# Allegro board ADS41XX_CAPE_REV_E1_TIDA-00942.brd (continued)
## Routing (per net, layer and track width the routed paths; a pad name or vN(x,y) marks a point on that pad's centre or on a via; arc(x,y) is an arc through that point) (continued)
P4.7V: length 8
  TOP w0.305: 39.75,105.28 39.92,105.12 U7.1
  TOP w0.508: C78.1 v1(40.51,107.44) FB6.2 39.75,107.26 v1(39.75,106.05) 39.75,105.28 C79.1 R83.1
  vias: v1(38.48,108.84) v1(38.48,107.44) v1(38.73,106.05) v1(39.62,108.84) v1(40.26,105.41) v1(40.51,108.84) v1(40.51,106.55) v1(40.89,106.17) v1(41.53,108.84) v1(41.66,106.17)
VDD_5V: length 16.1
  PWR2 w0.559: J6.5 53.49,23.98 ; J6.5 53.49,25.55 ; J6.5 51.92,23.98 ; J6.5 51.92,25.55 ; JP4.1 44.64,34.35 ; JP4.1 42.99,32.7 ; JP4.1 43.81,34.67 43.69,34.8 ; JP4.1 43.81,32.89 43.43,32.51 ; JP4.1 44.64,32.7 ; JP4.1 42.99,34.35 ; 49.38,25.55 J6.6 ; J6.6 50.95,25.55 ; J6.6 49.38,23.98 ; J6.6 50.95,23.98
VIN-: length 5.3
  TOP w0.381: v1(25.78,92.2) 26.26,92.69 U6.2 26.26,95.99 R57.1
  BOTTOM w0.381: R16.1 v1(25.78,92.2)
AIN_P: length 3.2
  TOP w0.381: R9.2 24.99,95.94 C11.1 U6.3
AINP: length 13
  TOP w0.381: C62.1 R56.2 ; R56.2 R10.1 ; R56.2 JP5.1 J1.1
AVP: length 4.6
  TOP w0.381: R9.1 D1.3 R10.2
B+: length 1.2
  TOP w0.279: U5.10 24.89,72.49 R1.1
B-: length 1.2
  TOP w0.279: R3.1 25.39,72.46 U5.11
BBB-CLKOUT: length 51.8
  TOP w0.178: v1(42.8,48.51) 46.62,48.51 46.71,48.6 49.19,48.6 J6.24 50.16,50.16 ; RN2.16 v1(11.51,40.59)
  BOTTOM w0.178: v1(42.8,48.51) 39.37,45.09 31.88,45.09 31,44.21 31,40.65 29.84,39.5 27.81,39.5 25.91,37.59 13.08,37.59 11.51,39.17 v1(11.51,40.59)
BBB-D0: length 27.5
  TOP w0.178: 4.45,75.56 8.76,75.56 10.79,73.53 10.79,57.15 12.98,54.97 RN1.9
BBB-D1: length 30.1
  TOP w0.178: RN1.10 12.29,53.34 10.03,55.6 10.03,72.39 8.26,74.17 3.3,74.17 1.91,75.56
BBB-D2: length 26.1
  TOP w0.178: 4.45,73.03 7.37,73.03 9.4,70.99 9.4,55.42 12.29,52.53 RN1.11
BBB-D3: length 28.6
  TOP w0.178: 1.91,73.03 3.17,71.75 7.11,71.75 8.89,69.98 8.89,55.12 12.29,51.71 RN1.12
BBB-D4: length 25
  TOP w0.178: 4.45,70.48 6.99,70.48 8.26,69.22 8.26,54.94 12.29,50.9 RN1.13
BBB-D5: length 27.8
  TOP w0.178: RN1.14 12.29,50.09 7.75,54.64 7.75,68.71 7.37,69.09 3.3,69.09 1.91,70.48
BBB-D6: length 23
  TOP w0.178: RN1.15 12.29,49.28 7.11,54.46 7.11,65.91 5.08,67.94 4.45,67.94
BBB-D7: length 25.8
  TOP w0.178: RN1.16 12.29,48.46 6.6,54.15 6.6,65.53 5.46,66.67 3.17,66.67 1.91,67.94
BBB-D8: length 11.2
  TOP w0.178: RN2.9 10.87,46.28 4.45,52.7
BBB-D9: length 15.1
  TOP w0.178: RN2.10 13.67,45.47 13.84,45.64 13.84,47.07 13.67,47.24 12.45,47.24 4.45,55.24
BBB-D10: length 17.2
  TOP w0.178: RN2.11 7.67,44.65 6.1,46.23 3.68,46.23 2.92,46.99 2.92,51.31 1.91,52.32 1.91,52.7
BBB-D11: length 23.8
  TOP w0.178: 1.91,55.24 0.89,54.23 0.89,44.07 1.12,43.84 RN2.12
BBB-SCLK: length 70.9
  TOP w0.178: U11.6 15.99,88 16.76,88.77 v1(17.65,89.53)
  BOTTOM w0.178: v1(17.65,89.53) 17.87,89.75 18.12,89.75 19.16,90.79 24.09,90.79 24.65,91.35 25.34,91.35 25.57,91.12 25.89,91.12 26.01,91 26.38,91 26.58,90.79 46.33,90.79 48.59,88.53 48.59,86.92 49.14,86.37 49.14,83.36 48.01,82.23 48.01,78.36 49.02,77.34 49.02,59.56 49.53,59.05 51.44,59.05 52.7,57.78
BBB-SDATA: length 81.5
  TOP w0.178: U11.10 11.46,89 v1(11.43,91.44)
  BOTTOM w0.178: v1(11.43,91.44) 11.44,91.45 17.39,91.45 17.65,91.19 24.02,91.19 24.52,91.68 25.47,91.68 25.7,91.45 26.02,91.45 26.15,91.33 26.51,91.33 26.65,91.19 48.13,91.19 48.64,90.68 48.64,88.95 48.92,88.67 48.92,87.73 49.53,87.12 49.53,84.23 49.47,84.16 49.47,83.48 49.53,83.41 49.53,80.92 49.47,80.86 49.47,80.18 49.53,80.11 49.53,78.23 51.44,76.33 51.44,60.07 52.58,58.93 53.21,58.93 53.59,58.55 53.59,58.28 53.68,58.19 53.68,57.38 53.59,57.29 53.59,56.64 53.34,56.39 51.31,56.39 50.16,55.24
BBB-SDOUT: length 94.6
  TOP w0.178: U11.13 v1(10.29,87)
  BOTTOM w0.178: v1(10.29,87) 7.37,87 6.6,87.76 6.6,91.31 7.75,92.46 10.16,92.46 10.92,91.69 10.92,91.19 11.3,90.81 11.56,90.81 11.87,91.12 15.18,91.12 17.26,89.04 18.94,89.04 19.32,89.42 21.22,89.42 21.84,90.04 23.81,90.04 24.79,91.02 25.2,91.02 25.43,90.79 25.75,90.79 25.99,90.55 26.35,90.55 26.86,90.04 30.86,90.04 30.99,89.92 33.59,89.92 33.7,89.8 34.43,89.8 35.05,90.42 45.72,90.42 48.26,87.88 48.26,84.84 48.25,84.82 48.25,84.44 47.24,83.44 47.24,77.09 48.59,75.74 48.59,61.33 48.39,61.13 48.39,57.4 49.02,56.77 49.02,54.48 49.53,53.98 51.44,53.98 52.7,55.24
BBB-SEN: length 65.9
  TOP w0.178: v1(42.42,83.82) 36.58,83.82 36.45,83.69 35.75,83.69 35.38,83.32 31.99,83.32 v1(31.62,83.69) ; U11.3 v1(15.23,86.5)
  BOTTOM w0.178: v1(31.62,83.69) 31.37,83.95 26.42,83.95 23.11,87.25 15.98,87.25 v1(15.23,86.5) ; v1(42.42,83.82) 44.2,82.04 44.2,77.6 44.96,76.83 45.97,76.83 47.37,75.44 47.5,75.44 48.26,74.68 48.26,61.47 47.37,60.58 47.37,57.53 48.39,56.52 48.39,53.98 49.66,52.7 50.16,52.7
CLK: length 1.4
  TOP w0.381: R25.1 U14.4
CLK+: length 10.7
  TOP w0.178: JP9.1 32.26,62.36
  TOP w0.279: 28.83,60.17 U1.10
  TOP w0.381: 28.83,60.17 30.86,60.17 arc(31.94,60.62) 32.38,61.69 JP9.1 32.38,64.01 33.53,65.15 C8.2
CLK-: length 2.2
  TOP w0.279: C10.1 28.7,60.96 28.41,60.67 U1.11
CLK_P: length 2.5
  TOP w0.381: U14.2 Y1.3
CLKOUT: length 17.9
  BOTTOM w0.178: R27.1 29.58,56.25 29.58,53.61 30.67,52.51 30.67,42.86 29.59,41.78 27.16,41.78 U3.23
CLOCK: length 3.9
  TOP w0.381: Y1.1 R24.2 39.88,57.15 JP7.1
CLOCKIN: length 11.7
  TOP w0.381: R18.1 44.07,78.81 arc(45.05,81.19) 47.42,82.17 J3.1
CN: length 15.7
  TOP w0.381: R18.2 44.07,73.51 arc(44,73.18) 43.81,72.9 arc(43.11,72.43) 42.28,72.26 37.34,72.26 arc(35.81,71.63) 35.18,70.1 JP8.3
CP: length 6.4
  TOP w0.381: R25.2 41.66,69.85 arc(40.67,69.44) 40.26,68.45 JP8.1
D0: length 8.2
  TOP w0.178: U1.37 20.87,53.51 v1(20.83,53.47)
  BOTTOM w0.178: U3.2 24.72,52.24 23.5,53.47 v1(20.83,53.47)
D1: length 8.3
  TOP w0.178: U1.38 21.34,54.86 v1(21.34,52.83)
  BOTTOM w0.178: U3.3 22.43,51.74 v1(21.34,52.83)
D2: length 9.5
  TOP w0.178: v1(21.78,50.74) 21.78,52.57 21.83,52.63 21.83,54.85 U1.39
  BOTTOM w0.178: U3.5 v1(21.78,50.74)
D3: length 9.4
  TOP w0.178: U1.40 22.4,54.86 v1(22.4,50.24)
  BOTTOM w0.178: U3.6 v1(22.4,50.24)
D4: length 10.6
  TOP w0.178: v1(22.61,49.02) 22.61,49.66 22.87,49.92 22.87,50.01 22.9,50.03 22.9,50.45 22.87,50.47 U1.41
  BOTTOM w0.178: v1(22.61,49.02) 22.99,49.02 23.11,49.15 27.03,49.15 U3.8
D5: length 11.7
  TOP w0.178: U1.42 23.37,54.89 23.37,51.18 23.24,51.05 23.24,48.77 22.73,48.26 v1(22.73,48.13)
  BOTTOM w0.178: U3.9 23.34,48.74 v1(22.73,48.13)
D6: length 10.7
  TOP w0.178: U1.43 23.87,50.92 23.62,50.67 v1(23.62,47.88)
  BOTTOM w0.178: v1(23.62,47.88) 25.4,47.88 25.53,47.75 27.11,47.75 U3.11
D7: length 12.6
  TOP w0.178: v1(23.12,47.24) 23.74,47.24 24.13,47.62 24.13,50.67 24.38,50.93 24.38,54.88 U1.44
  BOTTOM w0.178: U3.12 v1(23.12,47.24)
D8: length 12
  TOP w0.178: v1(23.75,46.74) 24.46,47.45 24.46,50.37 24.87,50.78 U1.45
  BOTTOM w0.178: U3.13 27.11,46.74 v1(23.75,46.74)
D9: length 11.6
  TOP w0.178: v1(24.52,46.24) 24.52,47.04 24.79,47.31 24.79,50.19 25.4,50.8 25.4,54.87 U1.46
  BOTTOM w0.178: U3.14 v1(24.52,46.24)
D10: length 12.1
  TOP w0.178: v1(25.02,45.21) 25.02,47.07 25.12,47.17 25.12,50.05 25.87,50.81 U1.47
  BOTTOM w0.178: U3.16 27.09,45.21 v1(25.02,45.21)
D11: length 14.8
  TOP w0.178: U1.48 26.37,54.15 v1(26.8,53.72)
  BOTTOM w0.178: U3.17 28.87,44.74 29.75,45.62 29.75,52.67 28.7,53.72 v1(26.8,53.72)
DATA_OE: length 49.7
  TOP w0.178: v1(20.92,41.24) 21.63,41.24 22.86,40.01 43.31,40.01 50.16,33.15 J6.12
  TOP w0.33: v1(20.92,41.24) R41.2
  BOTTOM w0.178: U3.48 20.62,52.74 21.08,52.28 21.08,50.29 21.46,49.91 21.46,41.78 v1(20.92,41.24)
  BOTTOM w0.33: U3.25 v1(20.92,41.24)
DBIN+: length 1
  TOP w0.381: L2.1 R1.2
DBIN-: length 1
  TOP w0.381: L3.1 R3.2
DBIN_N: length 3.6
  TOP w0.381: L3.2 25.63,68.4 R14.1 C56.2 25.63,65.35 R54.1
DBIN_P: length 3.6
  TOP w0.381: R53.1 24.61,65.35 C56.1 R14.2 24.61,68.4 L2.2
DFS: length 7.1
  TOP w0.178: JP6.2 32.77,58.29 31.68,58.29 31.67,58.31 30.82,58.31 30.8,58.29 29.59,58.29 29.47,58.17 U1.6
I2C2_SCL: length 50.5
  TOP w0.178: R20.2 v1(45.09,86.23) U15.6
  PWR1 w0.178: v1(45.09,86.23) 45.09,86.11 49.01,82.18 49.01,80.57 48.9,80.45 48.9,44.5 49.58,43.81 51.44,43.81 J6.19
I2C2_SDA: length 47.2
  TOP w0.178: R15.2 45.85,84.96 v1(45.09,84.96) U15.5
  PWR1 w0.178: J6.20 50.04,42.55 48.41,44.17 48.41,79.73 45.09,83.06 v1(45.09,84.96)
IN+: length 9.4
  TOP w0.279: C3.2 25.39,76.84 U5.2
  TOP w0.381: C3.2 25.64,79.11 v1(26.04,79.5) ; R6.2 C2.1 29.13,79.58 v1(29.21,79.5)
  BOTTOM w0.381: v1(26.04,79.5) v1(29.21,79.5)
IN-: length 5.1
  TOP w0.279: U5.3 24.89,76.84 C3.1
  TOP w0.381: C99.1 R5.2 23.3,78.61 24.26,78.61 24.63,78.24 C3.1
IN_M: length 2.5
  TOP w0.178: U1.16 24.87,62.63 24.97,62.73 24.97,63.73 R53.2
IN_P: length 2.5
  TOP w0.178: R54.2 25.27,63.73 25.27,62.73 25.37,62.63 U1.15
INM: length 3.6
  TOP w0.381: R7.1 27.15,79.71 R6.1 C1.2 R11.1
INP: length 6.9
  TOP w0.381: R8.2 24.99,80.85 C1.1 R17.1 23.25,80.82 R5.1
N4.7V:
  vias: v1(4.57,99.31) v1(5.71,99.31) v1(6.6,99.57) v1(6.99,100.71) v1(6.99,98.81) v1(7.11,100.08) v1(7.11,97.92) v1(7.24,99.44) v1(7.62,98.68) v1(7.75,99.95) v1(7.87,100.71)
OUT+: length 7.4
  TOP w0.381: v1(24.99,90.53) U6.6 24.99,86.79 R8.1
  BOTTOM w0.381: v1(24.99,90.53) 25.99,89.53 26.67,89.53 R16.2
OVR/SDOUT: length 45.7
  TOP w0.178: TP3.1 33.02,51.56 30.86,53.72 30.86,55.37 29.56,56.67 v1(28.57,56.67) U1.3 ; U10.11 12.23,73.49 13.84,71.88 13.84,69.34 v1(14.1,69.09)
  BOTTOM w0.178: v1(14.1,69.09) 21.84,69.09 22.35,68.58 28.96,68.58 29.59,67.94 29.59,65.66 29.34,65.41 29.34,58.67 28.45,57.78 28.45,56.8 v1(28.57,56.67)
RESET: length 39.2
  TOP w0.178: U1.30 v1(14.47,58.67) ; v1(2.79,84.2) 5.07,84.2 U13.4
  BOTTOM w0.178: v1(2.79,84.2) R88.2 2.79,77.39 2.97,77.22 4.45,77.22 10.73,70.93 10.73,63.18 14.47,59.44 v1(14.47,58.67)
SCLK: length 23.6
  TOP w0.178: U10.13 13.46,77.11 v1(13.46,75.31) ; v1(16.51,59.17) U1.29
  BOTTOM w0.178: v1(13.46,75.31) 13.08,74.93 13.08,65.79 TP16.1 16.51,61.34 v1(16.51,59.17)
SDATA: length 34.7
  TOP w0.178: U1.28 17.04,59.67 15.49,61.21 15.49,63.25 17.53,65.28 TP17.1 14.73,68.2 14.73,72.39 12.88,74.24 U10.12 12.88,78.81 11.94,79.76 5.97,79.76 JP1.2
SEN: length 24.4
  TOP w0.178: U1.27 17.81,60.17 17.02,60.96 17.02,62.36 17.91,63.25 19.56,63.25 20.07,63.75 20.07,67.94 TP15.1 16.71,71.12 14.18,73.65 U10.14
SPARE1: length 7.8
  TOP w0.178: 1.91,34.92 3.17,33.66 6.74,33.66 7.38,33.02 PP5.1
SPARE2: length 7.8
  TOP w0.178: PP4.1 7.38,38.1 6.74,38.73 3.17,38.73 1.91,37.47
SPI-ACT: length 16.1
  TOP w0.178: 9.4,84.84 9.4,86.23 8.81,86.82 U13.1 ; U10.9 v1(9.56,77.19) ; 9.4,82.3 9.4,81.41 v1(9.56,81.25) 7.4,81.25 JP3.1
  TOP w0.254: 9.4,84.84 9.4,83.95 R86.2 9.4,82.93 9.4,82.3
  BOTTOM w0.178: v1(9.56,77.19) v1(9.56,81.25)
SW1_A0: length 7.2
  TOP w0.178: SW1.4 37.59,91.19 38.58,90.2 U15.1 36.2,88.77 R26.2
SW1_A1: length 13.1
  TOP w0.178: R23.2 36.2,87.5 U15.2 40.13,87.5 40.64,88.01 40.64,92.46 38.86,94.23 SW1.3
SW1_A2: length 2.5
  TOP w0.178: U15.3 R22.2
SYS_5V: length 27.7
  TOP w0.559: 37.91,34.35 JP4.3 ; JP4.3 37.91,32.7 ; JP4.3 38.73,34.92 ; JP4.3 38.73,32.51 38.61,32.38 ; J6.7 53.49,26.52 ; J6.7 51.92,28.09 ; J6.7 53.49,28.09 ; J6.7 51.92,26.52 ; 49.38,28.09 J6.8 ; J6.8 50.95,28.09 ; J6.8 50.95,26.52 ; J6.8 49.38,26.52
  TOP w1.524: J6.8 J6.7
  PWR2 w0.559: J6.7 53.49,28.09 ; J6.7 51.92,26.52 ; J6.7 51.92,28.09 ; 37.91,32.7 JP4.3 ; JP4.3 39.56,34.35 ; JP4.3 37.91,34.35 ; J6.8 50.95,28.09 ; J6.8 50.95,26.52 ; J6.8 49.38,26.52 ; J6.8 49.38,28.09
USB-SCLK: length 94.6
  TOP w0.178: U11.5 16.25,87.5 16.45,87.69 18.99,87.69 v1(19.18,87.88) ; U2.5 v1(43.28,23.22)
  BOTTOM w0.178: v1(43.28,23.22) 43.28,25.49 46.3,28.51 46.3,35.25 44.58,36.96 44.58,49.4 44.96,49.78 44.96,68.71 44.45,69.22 35.97,69.22 34.92,70.26 34.92,80.9 32.38,83.44 32.38,84.2 31.5,85.09 28.57,85.09 28.31,85.36 28.24,85.36 27.95,85.65 27.95,85.71 26.4,87.26 24.12,87.26 23.5,87.88 v1(19.18,87.88)
USB-SDATA: length 102.2
  TOP w0.178: U11.11 10.81,88 v1(10.79,88.01) ; U2.3 v1(44.58,23.24)
  BOTTOM w0.178: v1(10.79,88.01) 10.92,88.14 10.92,89.53 11.53,90.14 11.83,90.14 12.15,90.46 14.69,90.46 16.78,88.38 23.51,88.38 24.26,87.63 27.87,87.63 28.24,87.26 29.45,87.26 30.1,86.61 31.75,86.61 32.26,86.11 32.26,84.84 32.77,84.33 32.77,83.82 36.42,80.17 36.42,73.49 37.34,72.57 37.34,70.1 37.85,69.6 44.7,69.6 45.37,68.93 45.37,38.01 47.6,35.78 47.6,27.97 44.58,24.96 v1(44.58,23.24)
USB-SDOUT: length 111.7
  TOP w0.178: U2.1 v1(45.88,23.08) ; U11.14 v1(10.93,86.5)
  BOTTOM w0.178: v1(10.93,86.5) 10.93,87.11 10.03,88.01 7.37,88.01 7.11,88.27 7.11,91.06 7.87,91.82 10.16,91.82 10.59,91.39 10.59,91.05 11.17,90.47 11.69,90.47 12.01,90.79 15,90.79 17.08,88.71 23.81,88.71 24.38,88.14 27.66,88.14 27.8,88.28 29.22,88.28 29.35,88.4 31.1,88.4 32.64,86.87 32.64,85.22 37.23,80.63 37.23,79.61 41.91,74.93 43.94,74.93 44.7,74.17 44.7,73.15 46.1,71.75 46.1,59.36 45.93,59.19 45.93,58.78 46.1,58.61 46.1,39.12 48.9,36.32 48.9,27.43 45.88,24.42 v1(45.88,23.08)
USB-SEN: length 96.6
  TOP w0.178: U2.11 v1(39.38,23.23) ; U11.2 15.98,86 v1(16,85.98)
  BOTTOM w0.178: v1(16,85.98) 16.89,86.87 22.86,86.87 26.23,83.5 30.42,83.5 32.38,81.53 32.38,73.09 32.13,72.84 32.13,69.98 33.22,68.88 36.59,68.88 44.3,68.88 44.45,68.73 44.45,56.52 43.43,55.5 43.43,49.78 43.94,49.28 43.94,35.94 45.72,34.16 45.72,28.83 40.12,23.23 v1(39.38,23.23)
VCM: length 22.3
  TOP w0.178: U5.9 24.31,72.9 v1(23.24,72.9) ; v1(29.72,70.87) 29.72,66.29 27.94,64.52 27.94,64.14 26.8,62.99 v1(26.54,62.99) 26.37,62.82 U1.13
  TOP w0.381: U5.9 22.44,72.97 21.98,72.52
  BOTTOM w0.178: v1(26.54,62.99) 26.54,62.38 C21.1 ; v1(23.24,72.9) 24.26,71.88 28.32,71.88 29.34,70.87 v1(29.72,70.87)
N10245644: length 2.6
  TOP w0.178: v1(28.96,57.4) 28.69,57.67 U1.5
  BOTTOM w0.178: v1(28.96,57.4) 29.46,57.4 R27.2
N18756746: length 7.3
  TOP w0.254: U2.16 38.08,13.55 38.16,13.47 38.16,13.32 38.35,13.13 38.57,13.13 38.73,12.97 38.73,12.82 38.8,12.75 38.8,11.8 39.65,10.95 C26.1 39.65,10.27 39.71,10.21 J4.2
N18756762: length 11.3
  TOP w0.508: U2.20 40.68,13.04 40.89,12.83 43.69,12.83 FB1.2 46.25,11.3 46.27,11.32 C25.1 47.93,11.2 C24.1
N18756792: length 13.1
  TOP w0.381: U2.17 v1(38.73,16.26) ; U2.4 v1(43.93,17.66)
  BOTTOM w0.381: v1(43.93,17.66) 43.28,17.02 39.49,17.02 v1(38.73,16.26) 38.73,15.23 38.84,15.13 C28.1
N18756806: length 11.4
  TOP w0.381: v1(36.58,14.48) 37.43,14.48 U2.15 ; J4.3 40.51,10.03 40.77,10.29 v1(40.77,11.3) 39.65,12.42 C27.1
  BOTTOM w0.381: v1(36.58,14.48) 39.75,11.3 v1(40.77,11.3)
N18756812: length 14.7
  TOP w0.381: v1(35.56,11.05) C23.1 36.51,11.05 37.78,9.78 38.23,9.78 38.91,9.09 J4.1 ; FB1.1 v1(43.31,11.3)
  BOTTOM w0.381: v1(35.56,11.05) 36.07,10.54 41.66,10.54 42.42,11.3 v1(43.31,11.3)
N18789804: length 4.1
  TOP w0.381: R44.2 24.65,31.35 U4.3
  TOP w0.508: R44.2 R46.1 C41.2
N19612134: length 5.1
  TOP w0.178: RN2.6 v1(15.88,44.65)
  BOTTOM w0.178: v1(15.88,44.65) 16.46,45.24 U3.33
N19612140: length 5.2
  TOP w0.178: RN2.7 v1(15.88,45.47)
  BOTTOM w0.178: v1(15.88,45.47) 16.65,46.24 U3.35
N19612162: length 5
  TOP w0.178: RN2.8 v1(15.88,46.28)
  BOTTOM w0.178: U3.36 16.34,46.74 v1(15.88,46.28)
N19612190: length 5.2
  TOP w0.178: RN2.5 v1(15.88,43.84)
  BOTTOM w0.178: U3.32 16.77,44.74 v1(15.88,43.84)
N19612194: length 5.7
  TOP w0.178: RN1.4 v1(15.88,50.9)
  BOTTOM w0.178: v1(15.88,50.9) 16.64,50.14 16.64,49.85 17.24,49.24 U3.41
N19612196: length 5.3
  TOP w0.178: RN1.1 v1(15.88,48.46)
  BOTTOM w0.178: U3.37 17.1,47.24 v1(15.88,48.46)
N19612206: length 5.3
  TOP w0.178: RN2.1 v1(15.88,40.59)
  BOTTOM w0.178: U3.26 17.03,41.74 v1(15.88,40.59)
N19612209: length 5.4
  TOP w0.178: RN1.5 v1(15.88,51.71)
  BOTTOM w0.178: v1(15.88,51.71) 17.35,50.24 U3.43
N19612211: length 5.5
  TOP w0.178: RN1.2 v1(15.88,49.28)
  BOTTOM w0.178: U3.38 17.41,47.74 v1(15.88,49.28)
N19612213: length 5.6
  TOP w0.178: RN1.8 v1(15.88,54.15)
  BOTTOM w0.178: U3.47 17.79,52.24 v1(15.88,54.15)
N19612215: length 5.4
  TOP w0.178: RN1.3 v1(15.88,50.09)
  BOTTOM w0.178: v1(15.88,50.09) 17.22,48.74 U3.40
N19612245: length 5.6
  TOP w0.178: RN1.6 v1(15.88,52.53)
  BOTTOM w0.178: v1(15.88,52.53) 17.66,50.74 U3.44
N19612247: length 5.5
  TOP w0.178: RN1.7 v1(15.88,53.34)
  BOTTOM w0.178: U3.46 17.47,51.74 v1(15.88,53.34)
N19618490: length 6.3
  TOP w0.33: R42.2 v1(26.04,34.8)
  TOP w0.381: U4.2 v1(25.15,32) R31.1
  BOTTOM w0.33: v1(25.15,32) 25.91,32 26.48,32.58 26.48,34.35 v1(26.04,34.8)
N19665097: length 3.2
  TOP w0.508: JP5.2 27.57,111.78 R55.1
N19665330: length 8.4
  TOP w0.279: U5.4 24.39,76.2
  TOP w0.381: R2.2 v1(23.75,76.84) 24.39,76.2 ; R17.2 22.23,80.88 v1(22.23,81.66)
  BOTTOM w0.381: v1(22.23,81.66) 23.75,80.13 v1(23.75,76.84)
N19665334: length 3.2
  TOP w0.279: U5.1 25.89,76.2
  TOP w0.381: 25.89,76.2 R4.2 27.15,78.44 R7.2
N19665338: length 1.1
  TOP w0.381: R4.1 C2.2
N19665444: length 3.2
  TOP w0.381: C99.2 21.79,79.58 21.34,79.12 21.34,77.72 21.59,77.47 R2.1
N19669855: length 1.7
  TOP w0.305: U7.6 46.05,103.81 C80.1
N19669869: length 5.1
  TOP w0.305: U7.2 39.95,104.47 39.75,104.27
  TOP w0.508: C79.2 38.61,104.14 R84.1 ; C79.2 39.75,104.27 ; C79.2 R83.2
N19670052:
  vias: v1(4.06,112.9) v1(4.06,112.14) v1(4.06,111.38) v1(4.06,110.62) v1(4.06,109.86) v1(4.06,109.09) v1(4.57,109.6) v1(4.7,113.41) v1(4.7,112.39) v1(4.95,109.09)
N19670056:
  vias: v1(7.37,111.76) v1(7.37,111.12) v1(8,112.01) v1(8.51,113.16) v1(8.51,112.27) v1(8.51,111.51)
N19670132: length 3.6
  TOP w0.381: U9.6 v1(9.68,104.3) ; v1(12.16,104.3) 12.16,103.79 C89.1
  GND2 w0.381: v1(9.68,104.3) v1(12.16,104.3)
N19670140: length 4
  TOP w0.305: C88.2 9.03,99.43 U9.2
  TOP w0.508: R13.1 C88.2 R12.2
N19683672: length 5.5
  BOTTOM w0.178: R19.1 34.16,55.12 JP6.1 R30.2
N19683688: length 3.3
  BOTTOM w0.178: 31.5,55.12 31.24,55.37 JP6.3 ; 31.5,55.12 R32.1 ; 31.5,55.12 R19.2
N19720857: length 48.4
  BOTTOM w0.178: 52.7,52.7 52.7,53.21 53.98,54.48 53.98,57.2 54.01,57.24 54.01,58.33 53.98,58.37 53.98,59.44 53.72,59.69 53.72,76.71 52.7,77.72 50.93,77.72 49.91,78.74 49.91,80.2 49.8,80.31 49.8,80.72 49.91,80.84 49.91,83.5 49.8,83.61 49.8,84.03 49.91,84.14 49.91,85.47 52.96,88.52 52.96,90.81 TP12.1
N19728178: length 7.8
  TOP w0.178: U11.7 v1(15.51,88.5) ; U10.4 v1(13.53,84.27)
  BOTTOM w0.178: v1(15.51,88.5) 14.71,88.5 14.35,88.14 14.35,86.11 13.53,85.29 v1(13.53,84.27)
N19728180: length 7.7
  TOP w0.178: U11.4 16.12,87 16.51,86.61 16.51,85.22 16.13,84.84 14.48,84.84 14.22,84.58 14.22,82.88 U10.3
N19728186: length 8.7
  TOP w0.178: U10.5 v1(12.88,84.84) ; v1(12.32,89.92) 12.32,89.12 U11.9
  BOTTOM w0.178: v1(12.32,89.92) 12.32,89.15 11.68,88.52 11.68,85.98 12.83,84.84 v1(12.88,84.84)
N19728192: length 8.1
  TOP w0.178: U11.12 9.77,87.5 9.65,87.37 9.65,86.74 10.16,86.23 10.16,85.22 10.79,84.58 11.81,84.58 12.23,84.16 U10.6
N19728318: length 6.3
  TOP w0.178: U11.1 v1(14.56,85.39)
  TOP w0.254: R85.1 JP2.2
  BOTTOM w0.178: JP2.2 17.06,85.39 v1(14.56,85.39)
N19728429: length 1.6
  BOTTOM w0.254: R87.2 7.75,77.85 JP1.1
N19730220: length 5.2
  TOP w0.254: PP6.1 47.62,73.2 49.15,71.68 49.23,71.68 50.16,70.74 50.16,70.48
N19734626: length 6
  TOP w0.178: J6.15 51.56,38.61 48.77,38.61 PP1.1
N19735928: length 9
  TOP w0.178: J6.23 51.49,46.41 44.59,46.41 PP3.1
N19735933: length 9.1
  TOP w0.178: PP2.1 51.05,51.56 51.82,50.8 52.07,50.8 52.7,50.16
N19737902: length 4.1
  TOP w0.381: C8.1 36.07,65.15 37.72,66.8 JP8.2
N19738595: length 2.1
  TOP w0.178: U12.3 6.1,88.76 U13.2
N19746144: length 7.8
  TOP w0.178: U15.7 45.97,87.5 47.24,88.77 R89.2 50.42,88.77 TP18.1
N19757494: length 2.4
  TOP w0.381: JP9.2 R21.1

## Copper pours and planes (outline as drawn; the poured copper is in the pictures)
1.8V on TOP: 19.56,33.78 19.56,32.51 26.29,32.51 26.29,33.78
1.8V on PWR1: 22.73,32.51 26.42,32.51 26.42,33.78 22.73,33.78
1.8V_IN on TOP: 19.43,30.23 19.43,21.72 21.72,21.72 21.72,23.75 24.13,23.75 24.13,31.75 18.16,31.75 18.16,30.23
1.8V_IN on PWR1: 19.43,29.97 19.43,23.75 24,23.75 24,29.84 23.5,30.35 19.81,30.35
5V_IN on TOP: 27.43,29.72 27.43,30.99 27.69,30.99 27.69,32.38 28.7,32.38 28.7,33.15 26.67,33.15 26.67,34.16 28.57,34.16 28.96,33.78 29.59,33.78 29.72,33.66 30.61,33.66 30.99,33.27 30.99,29.72
5V_IN on PWR1: 27.43,30.99 27.69,30.99 27.69,32.38 27.81,32.38 27.81,33.15 27.43,33.15 27.43,34.16 28.57,34.16 28.96,33.78 29.59,33.78 29.72,33.66 30.61,33.66 30.99,33.27 30.99,29.72 28.7,29.72
+1.8VA on TOP: 25.15,28.7 25.15,21.34 27.94,21.34 27.94,28.7
+1.8VA on PWR1: 25.15,22.86 25.15,21.46 27.94,21.46 27.94,26.16 27.05,26.16 25.65,27.56 24.51,27.56 24.51,23.5
+1.8VA on PWR2: 24.89,21.46 24.89,37.97 32.26,45.34 32.26,58.8 26.8,58.8 26.8,60.07 18.29,60.07 15.11,63.25 15.11,65.15 18.16,68.2 29.21,68.2 29.21,68.33 29.34,68.2 37.27,68.2 37.27,64.33 37.34,64.26 37.59,64.26 42.55,59.31 42.55,43.69 35.18,36.32 35.18,21.59 35.05,21.46
+1.8VD on TOP: 13.84,23.5 13.84,29.97 17.91,29.97 17.91,23.5
+1.8VD on PWR2: 12.47,23.27 12.47,23.37 5.84,23.37 5.84,74.8 3.81,74.8 3.81,90.93 16.26,90.93 16.26,82.8 44.45,82.8 45.72,81.53 45.72,65.66 45.09,65.02 40.64,65.02 38.73,66.93 38.73,73.28 11.3,73.28 11.3,57.66 31.75,57.66 31.75,47.37 23.5,39.12 23.5,23.27
+3.3V on BOTTOM: 33.66,89.03 33.66,84.33 48.13,84.33 48.13,89.03
+3.3V on BOTTOM: 10.41,85.6 10.41,82.17 16.76,82.17 16.76,78.11 15.62,78.11 15.62,76.58 18.8,76.58 19.05,76.83 19.05,82.17 22.48,82.17 22.48,85.6
+3.3V on BOTTOM: 37.72,56.77 37.72,63.75 42.29,63.75 42.29,56.77
+3.3V on PWR1: 16.38,40.26 16.38,60.83 14.86,62.36 14.86,67.82 10.29,72.39 10.29,87 11.68,88.39 21.34,88.39 22.1,87.63 22.1,84.07 19.3,81.28 19.3,73.53 24.38,68.45 38.61,68.45 38.67,68.39 40.7,68.39 42.93,66.17 42.93,54.23 49.02,48.13 49.02,30.48 53.72,30.48 53.98,30.23 53.98,19.94 45.85,19.94 45.72,20.07 45.72,36.96 35.18,47.5 35.18,65.15 26.54,65.15 21.34,59.94 21.34,40.26
+3.3V on PWR2: 18.29,90.42 18.29,84.07 48.51,84.07 48.51,90.42
+4.7V on TOP: 26.16,88.14 26.16,85.47 30.48,85.47 30.48,88.14
+4.7V on TOP: 24.1,73.55 22.72,73.55 22.49,73.78 21.67,73.78 21.67,74.6 20.7,75.56 20.32,75.56 20.32,76.96 21.46,76.96 21.67,76.75 21.67,76.96 22.74,76.96 23.12,76.58 23.12,75.95 23.72,75.34 24.1,75.34
+4.7V on BOTTOM: 23,75.56 23,73.79 24.14,73.79 24.14,75.56
+4.7V on PWR1: 24.77,72.01 23.37,73.41 21.59,73.41 21.59,77.22 26.67,77.22 29.46,80.01 29.46,84.58 26.42,84.58 26.42,88.27 29.46,88.27 30.35,89.15 30.35,91.44 30.48,91.44 30.48,92.96 30.35,92.96 30.35,100.46 29.72,101.09 29.72,103.12 26.67,103.12 26.67,103.89 29.72,103.89 29.72,105.16 33.02,108.46 36.45,108.46 36.45,106.43 33.78,103.76 33.78,72.01
+5V on TOP: 9.78,106.68 9.78,109.35 9.27,109.86 8.13,109.86 8.13,110.36 9.14,110.36 9.46,110.68 9.46,111.95 9.53,112.01 11.3,112.01 11.3,106.68
+5V on TOP: 35.56,23.5 35.56,29.59 37.34,31.37 38.48,31.37 38.54,31.43 38.8,31.43 40.01,32.64 40.01,34.67 42.55,34.67 42.55,31.75 42.67,31.62 46.1,31.62 46.1,29.08 39.75,29.08 39.24,29.59 38.35,29.59 37.72,28.96 37.72,23.5
+5V on TOP: 29.21,34.04 29.21,35.43 27.69,35.43 27.69,38.86 31.24,38.86 31.24,34.04
+5V on TOP: 43.94,106.68 46.35,106.68 46.35,109.98 46.48,110.11 49.28,110.11 50.55,108.84 50.55,99.06 43.94,99.06
+5V on PWR1: 45.59,23.24 30.35,23.24 29.08,21.97 0.76,21.97 0.76,121.41 53.85,121.41 53.85,87.38 46.35,87.38 40.13,81.15 40.13,51.05 45.59,45.59 ; 1 cut-out
+5V on PWR2: 43.94,106.68 50.55,106.68 50.55,99.06 43.94,99.06
-4.7V on TOP: 24.16,95.3 20.19,95.3 19.48,96.01 4.83,96.01 4.83,95.38 4.7,95.25 4.7,92.46 4.83,92.33 17.86,92.33 17.86,91.21 24.16,91.21
-4.7V on PWR2: 4.86,91.88 4.67,92.08 4.67,92.94 4.7,92.96 4.7,95.25 4.83,95.38 4.83,96.7 8.1,96.7 9.07,97.66 22.73,97.66 22.73,103.25 22.86,103.38 27.94,103.38 27.94,95 26.92,93.98 26.92,95.5 25.78,95.5 25.78,92.84 24.83,91.88
-5V on TOP, PWR2: 7.37,103.25 7.37,109.35 7.49,109.47 9.27,109.47 9.27,106.05 10.92,106.05 10.92,103.25 10.16,103.25 10.16,104.39 9.27,104.39 9.27,103.25
GND on TOP (solid shape): 10.23,102.7 11.26,102.7 11.26,102.42 10.23,102.42 10.23,102.05 11.26,102.05 11.26,101.77 10.23,101.77 10.23,101.49 8.48,101.49 8.48,101.77 7.46,101.77 7.46,102.05 8.48,102.05 8.48,102.42 7.46,102.42 7.46,102.7 8.48,102.7 8.48,102.99 10.23,102.99
GND on TOP (solid shape): 42.74,105.02 43.11,105.02 43.11,106.04 43.39,106.04 43.39,105.02 43.68,105.02 43.68,103.26 43.39,103.26 43.39,102.24 43.11,102.24 43.11,103.26 42.74,103.26 42.74,102.24 42.46,102.24 42.46,103.26 42.18,103.26 42.18,105.02 42.46,105.02 42.46,106.04 42.74,106.04
GND on TOP: 54.1,0.51 34.16,0.51 34.16,20.83 15.37,20.83 15.37,6.22 0.51,6.22 0.51,122.3 24.13,122.3 24.13,121.6 25.91,121.6 25.91,122.3 54.1,122.3 ; 19 cut-outs
GND on BOTTOM: 54.1,0.51 34.16,0.51 34.16,20.83 15.37,20.83 15.37,6.22 0.51,6.22 0.51,122.3 24.13,122.3 24.13,121.6 25.91,121.6 25.91,122.3 54.1,122.3 ; 25 cut-outs
GND on GND1, GND2: 54.1,0.51 34.16,0.51 34.16,20.83 15.37,20.83 15.37,6.22 0.51,6.22 0.51,122.3 24.13,122.3 24.13,121.6 25.91,121.6 25.91,122.3 54.1,122.3 ; 1 cut-out
P4.7V on TOP: 38.1,105.03 38.1,109.22 41.78,109.22 41.78,105.03
P4.7V on PWR2: 38.1,105.03 38.1,109.22 42.16,109.22 42.16,104.9 41.91,104.9 41.78,105.03
VDD_5V on PWR2: 46.1,35.05 46.1,25.78 53.98,25.78 53.98,21.34 53.85,21.34 53.98,21.21 53.98,20.07 44.32,20.07 41.4,22.99 41.4,33.78 42.67,35.05
N4.7V on TOP: 4.32,101.09 4.32,97.54 8.51,97.54 8.51,101.09
N4.7V on PWR2: 4.32,101.09 4.32,97.54 7.49,97.54 8.51,98.55 8.51,101.09
SYS_5V on TOP: 46.61,25.78 46.61,31.75 43.05,35.31 39.88,35.31 39.88,32.64 39.37,32.13 36.83,32.13 36.83,36.96 45.21,36.96 48.9,33.27 48.9,28.83 54.1,28.83 54.1,25.78
SYS_5V on PWR2: 46.74,35.43 40.64,35.43 40.64,32 37.08,32 37.08,37.85 37.34,37.85 38.35,38.86 52.2,38.86 52.2,29.72 53.72,28.19 53.72,26.29 46.74,26.29
N19670052 on TOP: 3.43,108.71 3.43,113.67 5.97,113.67 5.97,112.14 4.7,112.14 4.7,109.86 6.48,109.86 6.48,108.71
N19670052 on BOTTOM: 3.68,108.58 3.68,113.79 5.59,113.79 5.59,108.58
N19670056 on TOP: 6.99,110.87 6.99,113.67 9.02,113.67 9.02,110.87
N19670056 on BOTTOM: 7.24,110.49 6.86,110.87 6.86,112.9 7.49,113.54 9.27,113.54 9.27,110.49

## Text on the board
BOTTOM: BOTTOM SIDE
Board Geometry/Soldermask Bottom: SOLDERMASK BOTTOM
Ref Des/Silkscreen Bottom: SILKSCREEN BOTTOM | TIDA-00942 | REV E1 | ADS41     CAPE
User.Comments: ADS41XX_CAPE REV E1 | TIDA-00942 | 4. DO NOT TRIM THE LEADS OF J2, J5 AND J6.
TOP: TOP SIDE
Board Geometry/Soldermask Top: SOLDERMASK TOP
Ref Des/Silkscreen Top: SILKSCREEN TOP | TRIG | TWO'S | OFFSET
GND1: GROUND PLANE 1
PWR1: POWER PLANE 1
PWR2: POWER PLANE 2
GND2: GROUND PLANE 2
PLACE_BOUND_TOP: PASTEMASK TOP
DISPLAY_TOP: PASTEMASK BOTTOM
User.12: C61 | C9 | C12 | C28 | R30 | C20 | C6 | C7 | C13 | U3 | C19 | C53 | C22 | C15 | C54 | C101 | C51 | R87 | C104 | C103 | C102 | R88 | R19 | R32 | R27 | R16 | C21 | C14 | C18 | C17 | C16 | J2 | 1
User.13: FIGURE | SIZE | 10.0 | 12.0 | 13.0 | 38.0 | 40.0 | 63.0 | 125.0 | 39.0 | DRILL CHART: TOP to BOTTOM | ALL UNITS ARE IN MILS | PLATED | NON-PLATED | QTY | 969 | 35 | 20 | 110 | 9 | 6 | 4 | 2
